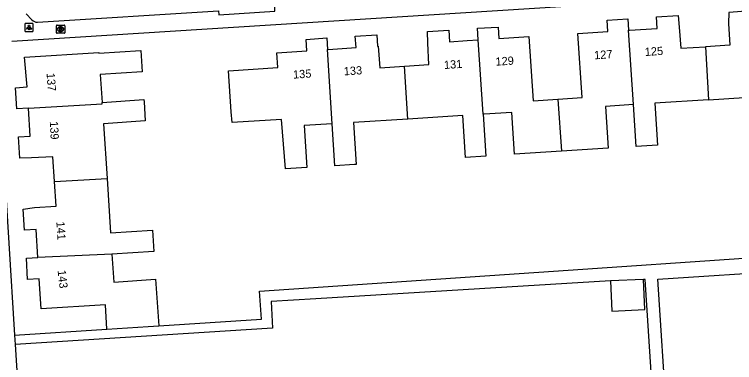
# Model space of a CAD drawing. Extents: x 159628 to 160723, y 388176 to 389416.
# Drawn here: x 160268.9 to 160356.5, y 388366.3 to 388408.6 of the extents above; entities that cross this region are included whole.
import ezdxf

# ---------------------------------------------------------------- set-up
doc = ezdxf.new("R2010")
doc.units = 0
for name, color, linetype in [('IMGEO_Brandkraan', 7, 'Continuous'), ('IMGEO_Lichtpunt', 7, 'Continuous'), ('IMGEO_Pand', 7, 'Continuous'), ('IMGEO_Pand_nummerreeks', 7, 'Continuous'), ('IMGEO_Voetpad_open', 7, 'Continuous')]:
    doc.layers.add(name, color=color, linetype=linetype)

msp = doc.modelspace()

# ---------------------------------------------------------------- linework, layer by layer
at = {"layer": 'IMGEO_Brandkraan'}
for p, q in [((160274.028, 388406.391), (160274.028, 388407.243)), ((160274.103, 388407.317), (160274.955, 388407.317)), ((160274.516, 388407.097), (160274.541, 388407.097)), ((160275.029, 388407.243), (160275.029, 388406.391)), ((160274.955, 388406.317), (160274.103, 388406.317)), ((160274.539, 388406.537), (160274.514, 388406.537))]:
    msp.add_line(p, q, dxfattribs=at)
for points in [[(160274.028, 388406.391), (160274.028, 388407.243)], [(160274.103, 388407.317), (160274.955, 388407.317)], [(160274.376, 388407.017), (160274.376, 388406.617), (160274.589, 388406.617)], [(160274.607, 388407.017), (160274.376, 388407.017)], [(160274.555, 388406.936), (160274.501, 388406.936), (160274.501, 388406.86)], [(160274.501, 388406.86), (160274.554, 388406.86)], [(160274.563, 388406.784), (160274.501, 388406.784), (160274.501, 388406.703)], [(160274.501, 388406.703), (160274.563, 388406.703)], [(160275.029, 388407.243), (160275.029, 388406.391)], [(160274.955, 388406.317), (160274.103, 388406.317)]]:
    msp.add_lwpolyline(points, dxfattribs=at)
for centre, radius, start, end in [((160274.105, 388407.241), 0.0765, 91.55205, 178.44795), ((160274.105, 388407.241), 0.0765, 91.55205, 178.44795), ((160274.556, 388406.898), 0.0379, 267.82845, 90.93552), ((160274.564, 388406.743), 0.0404, 269.87594, 90.50774), ((160274.595, 388406.868), 0.251, 268.66757, 293.53466), ((160274.611, 388406.872), 0.145, 59.4692, 91.53667), ((160274.636, 388406.919), 0.0922, 285.51372, 58.15012), ((160274.641, 388406.727), 0.105, 301.31148, 78.98903), ((160274.953, 388407.241), 0.0765, 1.55205, 88.44795), ((160274.953, 388407.241), 0.0765, 1.55205, 88.44795), ((160274.105, 388406.393), 0.0765, 181.55205, 268.44795), ((160274.105, 388406.393), 0.0765, 181.55205, 268.44795), ((160274.953, 388406.393), 0.0765, 271.55205, 358.44795), ((160274.953, 388406.393), 0.0765, 271.55205, 358.44795)]:
    msp.add_arc(centre, radius, start, end, dxfattribs=at)
for centre, major_axis, ratio, start_param, end_param in [((160274.515, 388406.817), (-0.387, 0.002), 0.722429, 4.712389, 7.853982), ((160274.54, 388406.817), (-0.39, 0.002), 0.717154, 1.570796, 4.712389)]:
    msp.add_ellipse(centre, major_axis=major_axis, ratio=ratio, start_param=start_param, end_param=end_param, dxfattribs=at)
at = {"layer": 'IMGEO_Lichtpunt'}
for p, q in [((160271.085, 388407.524), (160270.277, 388407.524)), ((160271.085, 388407.524), (160270.277, 388407.524)), ((160270.183, 388407.429), (160270.183, 388406.622)), ((160270.183, 388407.429), (160270.183, 388406.622)), ((160271.179, 388406.622), (160271.179, 388407.429)), ((160271.179, 388406.622), (160271.179, 388407.429)), ((160270.277, 388406.528), (160271.085, 388406.528)), ((160270.277, 388406.528), (160271.085, 388406.528))]:
    msp.add_line(p, q, dxfattribs=at)
for points in [[(160270.557, 388407.093), (160270.596, 388407.065), (160270.408, 388406.803), (160270.37, 388406.83), (160270.557, 388407.093)], [(160270.659, 388407.045), (160270.706, 388407.045), (160270.706, 388406.723), (160270.659, 388406.723), (160270.659, 388407.045)], [(160270.769, 388407.065), (160270.807, 388407.092), (160270.994, 388406.83), (160270.955, 388406.802), (160270.769, 388407.065)]]:
    msp.add_lwpolyline(points, dxfattribs=at)
msp.add_circle((160270.682, 388407.227), 0.0994, dxfattribs=at)
for centre, start, end in [((160270.277, 388407.429), 90, 180), ((160270.277, 388407.429), 90, 180), ((160271.085, 388407.429), 0, 90), ((160271.085, 388407.429), 0, 90), ((160270.277, 388406.622), 180, 270), ((160270.277, 388406.622), 180, 270), ((160271.085, 388406.622), 270, 0), ((160271.085, 388406.622), 270, 360)]:
    msp.add_arc(centre, 0.0946, start, end, dxfattribs=at)
at = {"layer": 'IMGEO_Pand'}
for points in [[(160343.564, 388406.684), (160343.678, 388406.692), (160347.056, 388406.922), (160346.972, 388408.317), (160349.581, 388408.471), (160349.719, 388407.086), (160349.934, 388404.502), (160352.907, 388404.691)], [(160361.917, 388407.891), (160361.725, 388407.879), (160360.868, 388407.826), (160358.427, 388407.674), (160358.343, 388409.033), (160355.744, 388408.859), (160355.727, 388407.507), (160355.884, 388404.88), (160352.907, 388404.691)], [(160334.967, 388398.304), (160337.923, 388398.503), (160337.409, 388406.304), (160341.053, 388406.534), (160340.98, 388407.935), (160343.471, 388408.076), (160343.564, 388406.684)], [(160316.325, 388402.322), (160319.277, 388402.509), (160319.16, 388405.132), (160319.121, 388406.53), (160321.727, 388406.7), (160321.819, 388405.302), (160323.955, 388405.438), (160325.305, 388405.524)], [(160325.305, 388405.524), (160325.214, 388406.932), (160327.708, 388407.082), (160327.798, 388405.685), (160331.461, 388405.921), (160331.986, 388398.104), (160334.967, 388398.304)], [(160344.168, 388397.64), (160343.564, 388406.684)], [(160307.539, 388395.302), (160304.144, 388395.086), (160304.469, 388389.994), (160301.874, 388389.829), (160301.391, 388395.832), (160295.4, 388395.45), (160295.268, 388396.78), (160294.925, 388401.768), (160300.919, 388402.158), (160300.802, 388403.956), (160304.447, 388404.176), (160304.362, 388405.57), (160306.891, 388405.756), (160306.977, 388404.361)], [(160306.977, 388404.361), (160307.054, 388404.366), (160310.443, 388404.577), (160310.355, 388405.973), (160312.96, 388406.149), (160313.035, 388404.744), (160313.143, 388404.751), (160313.318, 388402.132), (160316.325, 388402.322)], [(160325.893, 388396.474), (160325.305, 388405.524)], [(160270.612, 388397.194), (160269.211, 388397.115), (160269.047, 388399.699), (160270.456, 388399.816), (160270.161, 388403.397), (160279.183, 388403.99), (160279.196, 388403.887), (160284.293, 388404.237), (160284.44, 388401.65), (160279.347, 388401.317), (160279.57, 388397.922)], [(160307.539, 388395.302), (160306.977, 388404.361)], [(160352.907, 388404.691), (160353.298, 388398.223)], [(160316.742, 388395.89), (160316.325, 388402.322)], [(160353.298, 388398.223), (160360.072, 388398.655), (160360.397, 388393.564), (160362.78, 388393.716), (160362.47, 388398.808)], [(160270.612, 388397.194), (160279.584, 388397.723), (160279.57, 388397.922)], [(160279.57, 388397.922), (160284.661, 388398.254), (160284.678, 388397.99), (160284.83, 388395.658), (160279.738, 388395.324), (160280.173, 388388.659)], [(160334.967, 388398.304), (160335.398, 388391.968)], [(160353.298, 388398.223), (160346.764, 388397.806), (160347.089, 388392.714), (160344.493, 388392.549), (160344.168, 388397.64)], [(160273.799, 388388.298), (160273.608, 388391.293), (160270.986, 388391.175), (160269.584, 388391.136), (160269.422, 388393.713), (160270.823, 388393.801), (160270.612, 388397.194)], [(160344.168, 388397.64), (160340.774, 388397.424), (160341.099, 388392.332), (160335.398, 388391.968)], [(160325.893, 388396.474), (160326.223, 388391.383), (160323.738, 388391.224), (160323.413, 388396.316), (160316.742, 388395.89)], [(160335.398, 388391.968), (160329.718, 388391.606), (160329.393, 388396.697), (160326.008, 388396.481), (160325.893, 388396.474)], [(160316.742, 388395.89), (160310.134, 388395.468), (160310.459, 388390.377), (160310.261, 388390.364), (160307.864, 388390.211), (160307.539, 388395.302)], [(160271.773, 388379.044), (160271.555, 388382.454), (160270.15, 388382.364), (160269.982, 388384.946), (160271.373, 388385.134), (160273.99, 388385.299), (160273.799, 388388.298)], [(160273.799, 388388.298), (160280.173, 388388.659)], [(160280.173, 388388.659), (160280.605, 388382.055), (160285.696, 388382.388), (160285.866, 388379.791), (160280.773, 388379.458)], [(160280.773, 388379.458), (160271.773, 388379.044)], [(160280.773, 388379.458), (160280.995, 388376.063), (160286.087, 388376.396), (160286.457, 388370.724)], [(160280.168, 388370.312), (160279.971, 388373.307), (160272.154, 388372.795), (160271.926, 388376.453), (160270.526, 388376.366), (160270.369, 388378.955), (160271.773, 388379.044)], [(160345.396, 388376.378), (160341.385, 388376.193)], [(160341.385, 388376.193), (160341.554, 388372.526), (160345.565, 388372.711), (160345.396, 388376.378)], [(160280.168, 388370.312), (160285.158, 388370.639), (160286.457, 388370.724)]]:
    msp.add_lwpolyline(points, dxfattribs=at)
at = {"layer": 'IMGEO_Voetpad_open'}
for points in [[(160407.414, 388414.173), (160365.311, 388411.469), (160359.06, 388411.068), (160268.623, 388405.331)], [(160293.745, 388409.062), (160293.776, 388408.563), (160300.584, 388408.992), (160300.553, 388409.489)], [(160270.33, 388408.676), (160271.028, 388407.965)], [(160271.733, 388407.659), (160293.745, 388409.062)], [(160266.819, 388403.153), (160268.933, 388369.604)], [(160348.209, 388359.554), (160347.114, 388376.412), (160411.78, 388380.613), (160409.838, 388402.789)], [(160286.457, 388370.724), (160298.949, 388371.541), (160298.716, 388374.951), (160336.214, 388377.515), (160400.266, 388381.895)], [(160341.385, 388376.193), (160305.566, 388374.01), (160300.119, 388373.697), (160300.306, 388370.439), (160269.005, 388368.466)], [(160346.673, 388359.469), (160345.587, 388376.387), (160345.396, 388376.378)], [(160268.933, 388369.604), (160280.168, 388370.312)], [(160268.933, 388369.604), (160269.005, 388368.466)], [(160269.005, 388368.466), (160270.656, 388342.267)]]:
    msp.add_lwpolyline(points, dxfattribs=at)
msp.add_arc((160271.789, 388408.752), 1.095, 225.98805, 267.08616, dxfattribs=at)

# ---------------------------------------------------------------- texts
at = {"layer": 'IMGEO_Pand_nummerreeks'}
for s, rotation, p in [('127', 3.7586, (160339.416, 388403.149)), ('125', 3.7586, (160345.57, 388403.553)), ('131', 3.67839, (160321.161, 388401.972)), ('129', 3.67839, (160327.426, 388402.374)), ('133', 3.68412, (160308.984, 388401.196)), ('137', 274.10217, (160272.826, 388401.463)), ('135', 3.68412, (160302.814, 388400.799)), ('139', 272.99063, (160273.217, 388395.604)), ('141', 273.74912, (160274.013, 388383.394)), ('143', 276.37781, (160274.167, 388377.469))]:
    msp.add_text(s, height=1, rotation=rotation, dxfattribs=at).set_placement(p)

doc.saveas('drawing.dxf')
